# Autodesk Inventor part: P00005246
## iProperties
Created: 2008-08
Part Number: P00005246
Material: 1.0037 St 37-2
Document SubType Name: Modellieren
Designer: mttt
Manufacturer: Standard
Standards Organization: Custom
Author: mttt
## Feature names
1. Extrusion2
2. Bohrung1 [Hole]
